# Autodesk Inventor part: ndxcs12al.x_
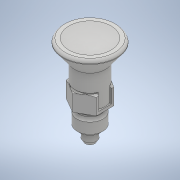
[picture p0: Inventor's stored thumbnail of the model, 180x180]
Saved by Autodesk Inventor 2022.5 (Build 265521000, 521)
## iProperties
Created: 2018-04
Part Number: ndxcs12al.x_
Material: 一般
Document SubType Name: Modeling
Designer: imaocorp
Density: 1 g/cm^3
Appearance: 既定
Sending System: SOLIDWORKS 2016-2016286
MC: AMD64
MC_MODEL: AMD64 Family 21 Model 2 Stepping 0, AuthenticAMD
OS: Windows_NT
FRU: Parasolid Version 28.0, build 224,  7-29-2016
FORMAT: text
GUISE: transmit
KEY: ndxcs12al
FILE: ndxcs12al.x_t
DATE: Wed Apr 25 10:17:13 2018
Author: imaocorp
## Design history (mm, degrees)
feature "Base1"
node "ソリッド1"
